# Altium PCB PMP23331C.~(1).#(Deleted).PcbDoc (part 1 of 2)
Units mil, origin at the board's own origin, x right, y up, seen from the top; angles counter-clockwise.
Board outline 3600 x 3375 mil, 4 copper layers (Top Layer, Signal Layer 1, Signal Layer 2, Bottom Layer), stack 39.6 mil thick; 105 components, 60 nets, 271 pads, 76 vias.
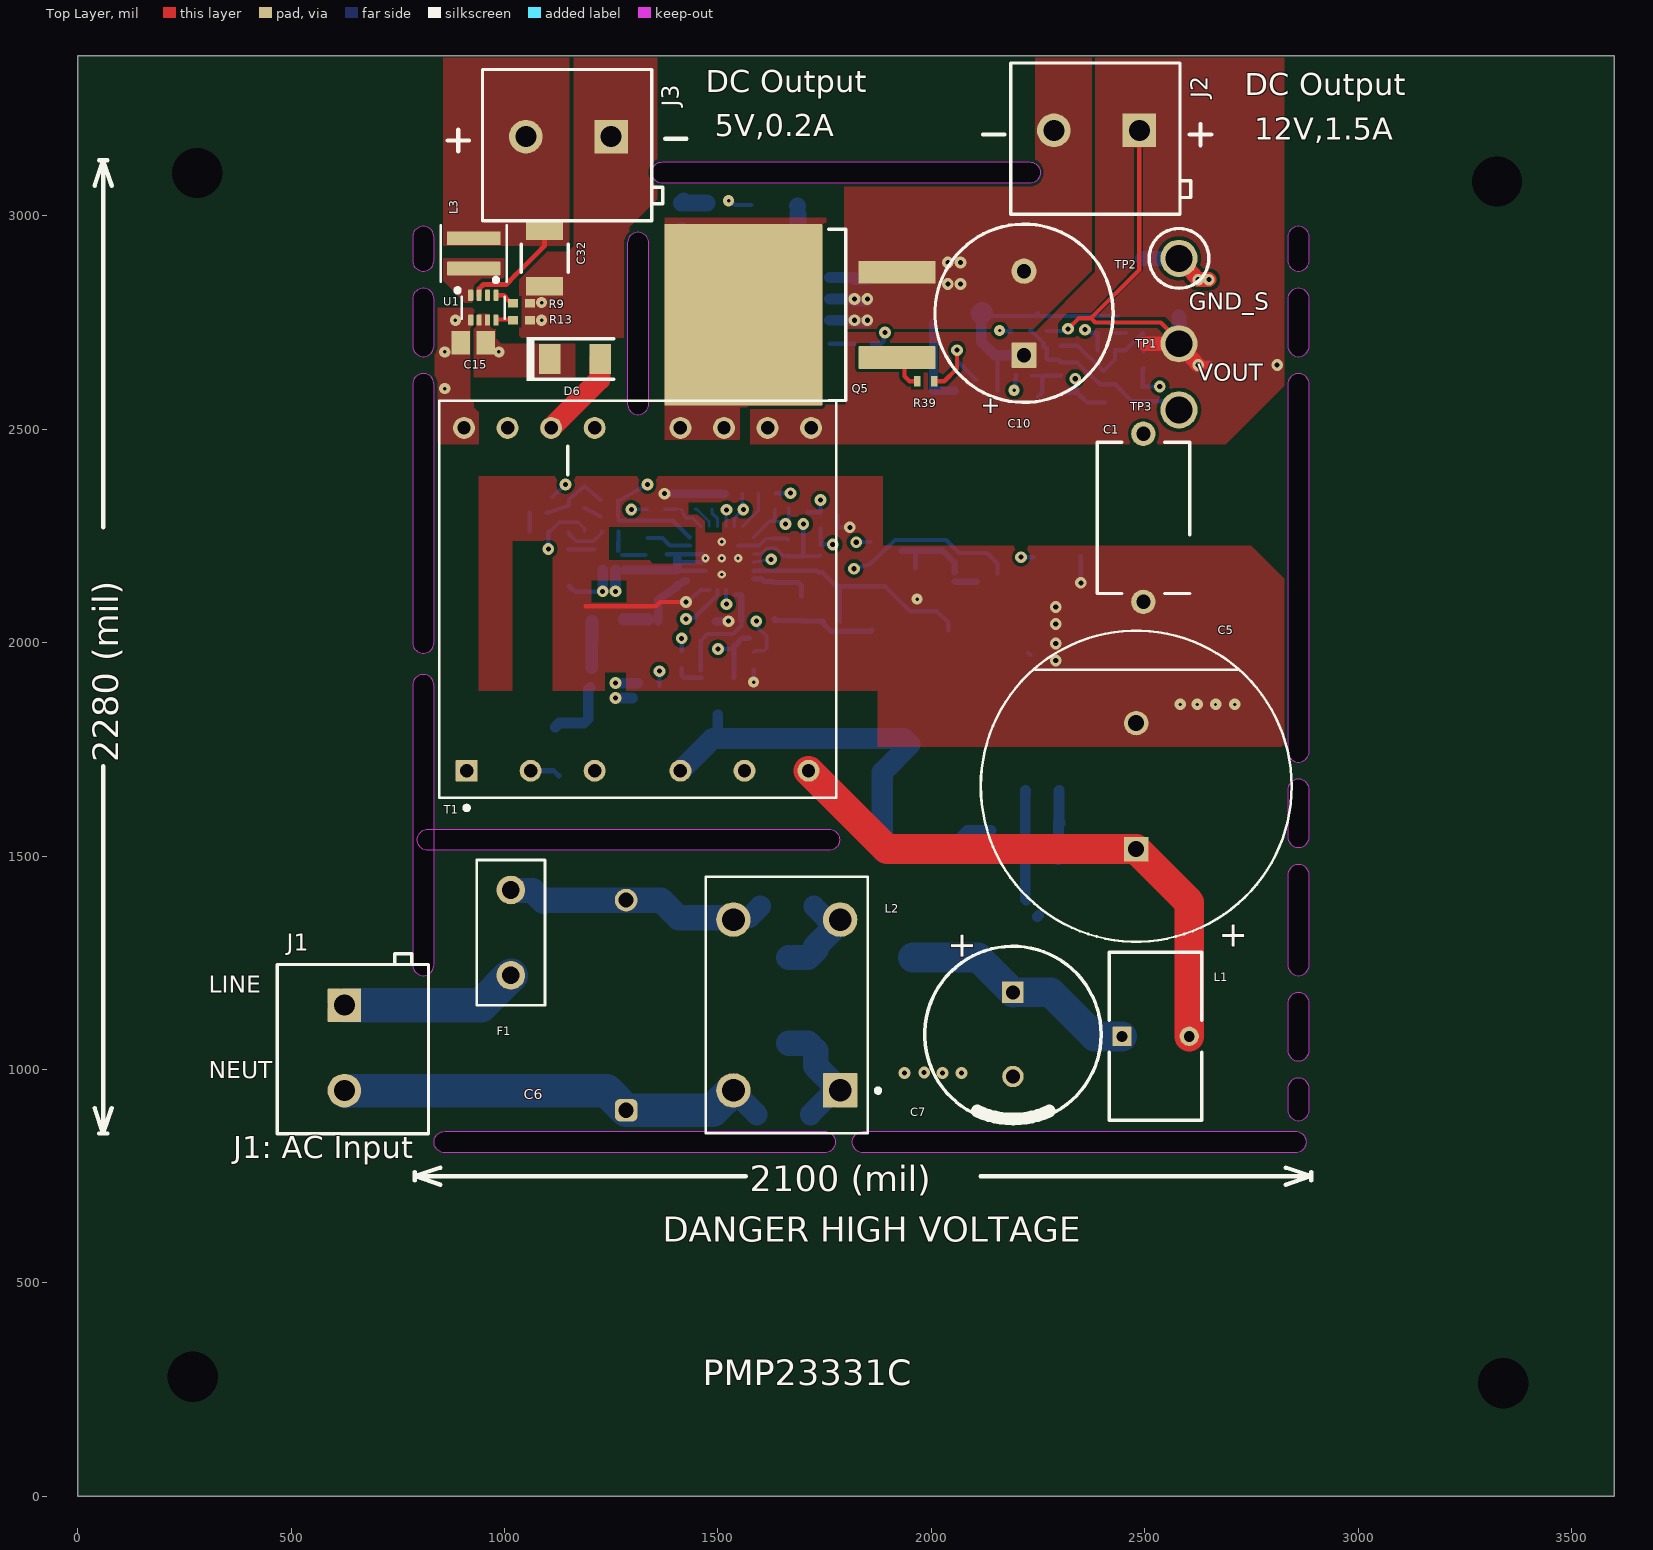
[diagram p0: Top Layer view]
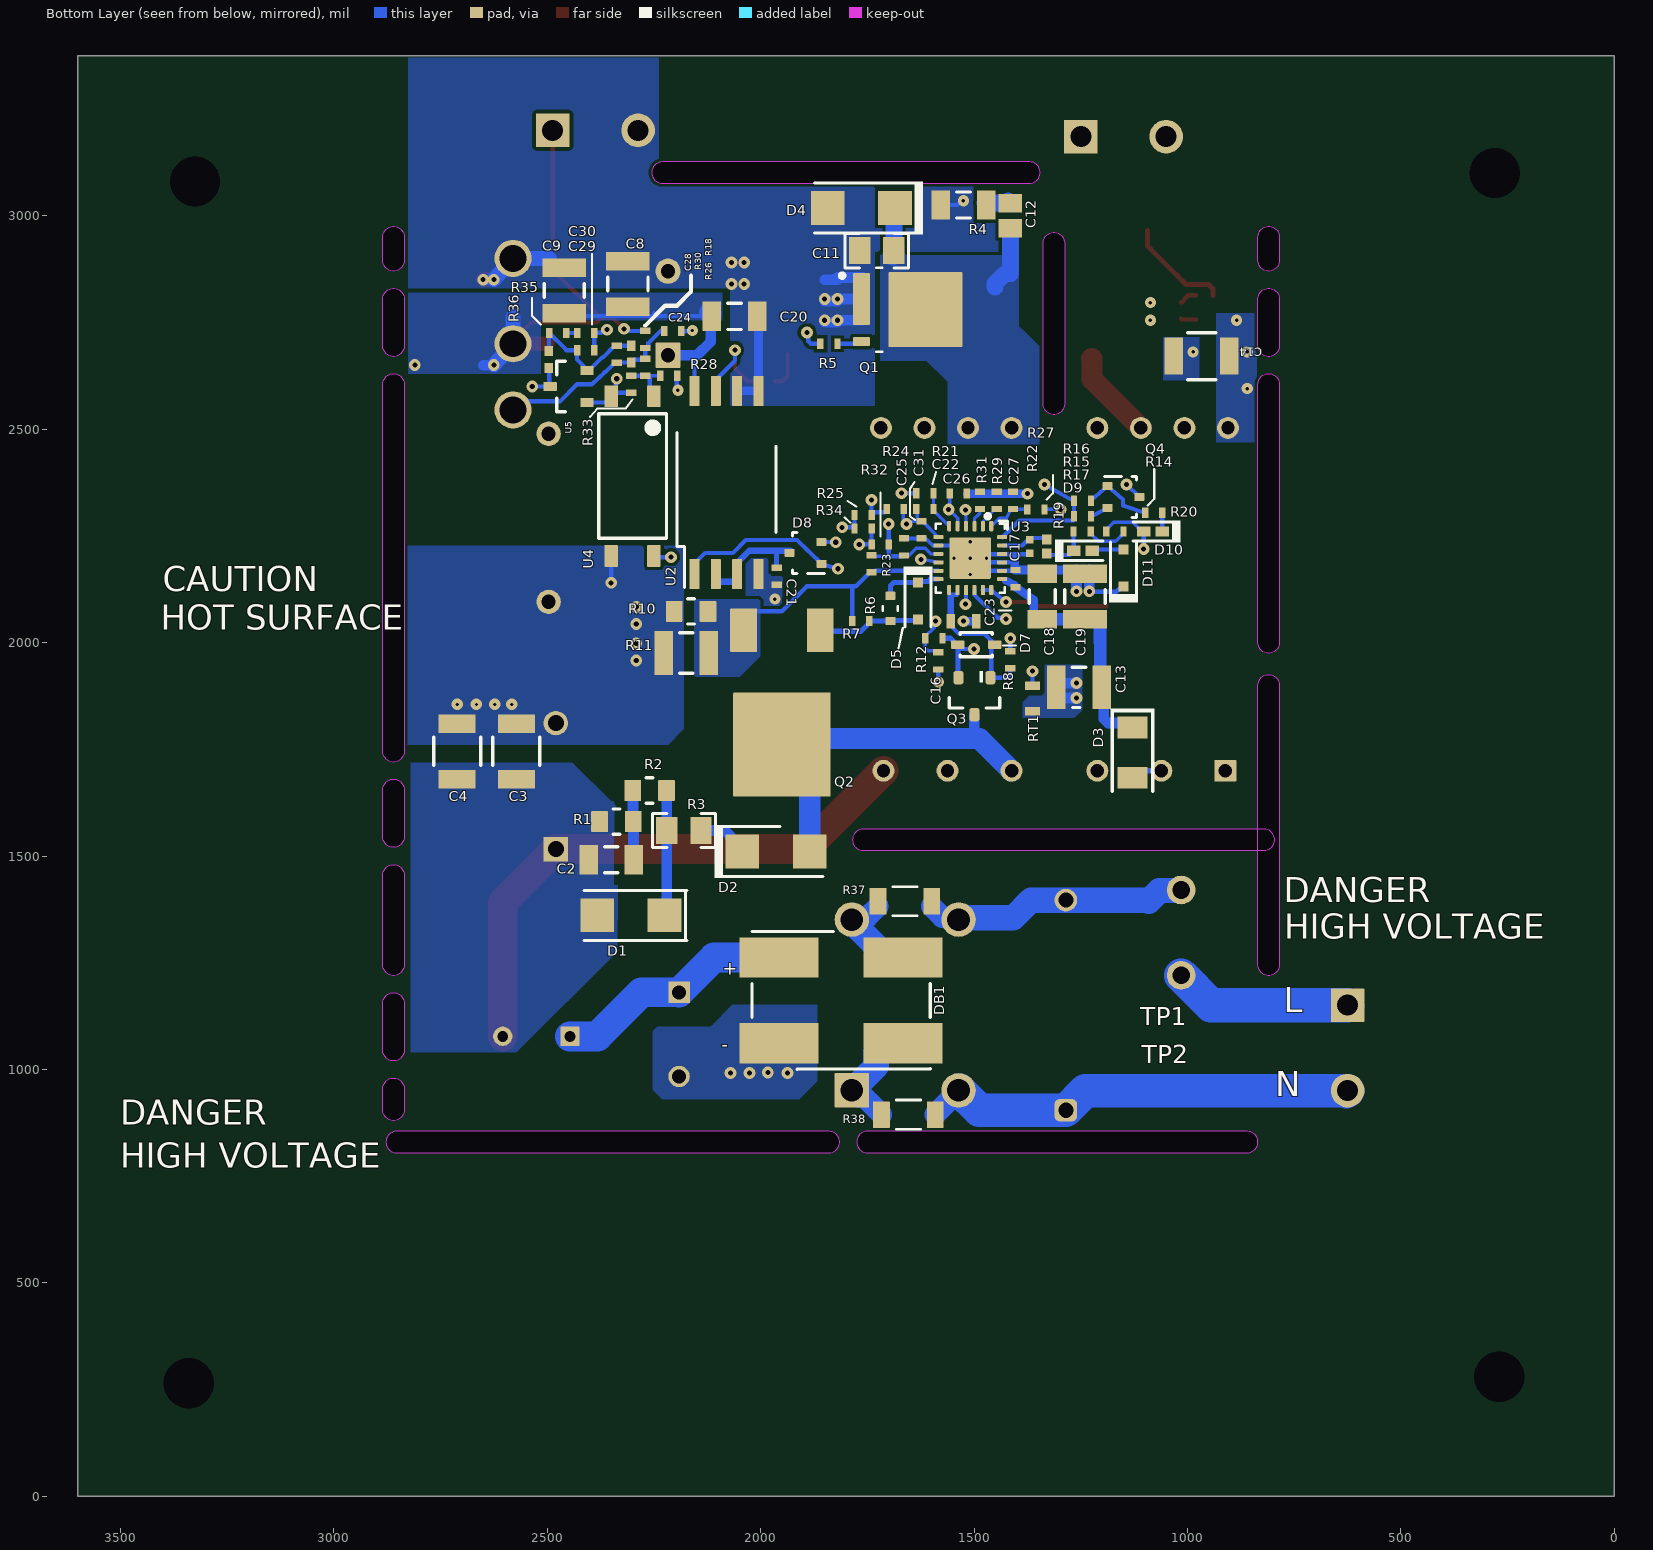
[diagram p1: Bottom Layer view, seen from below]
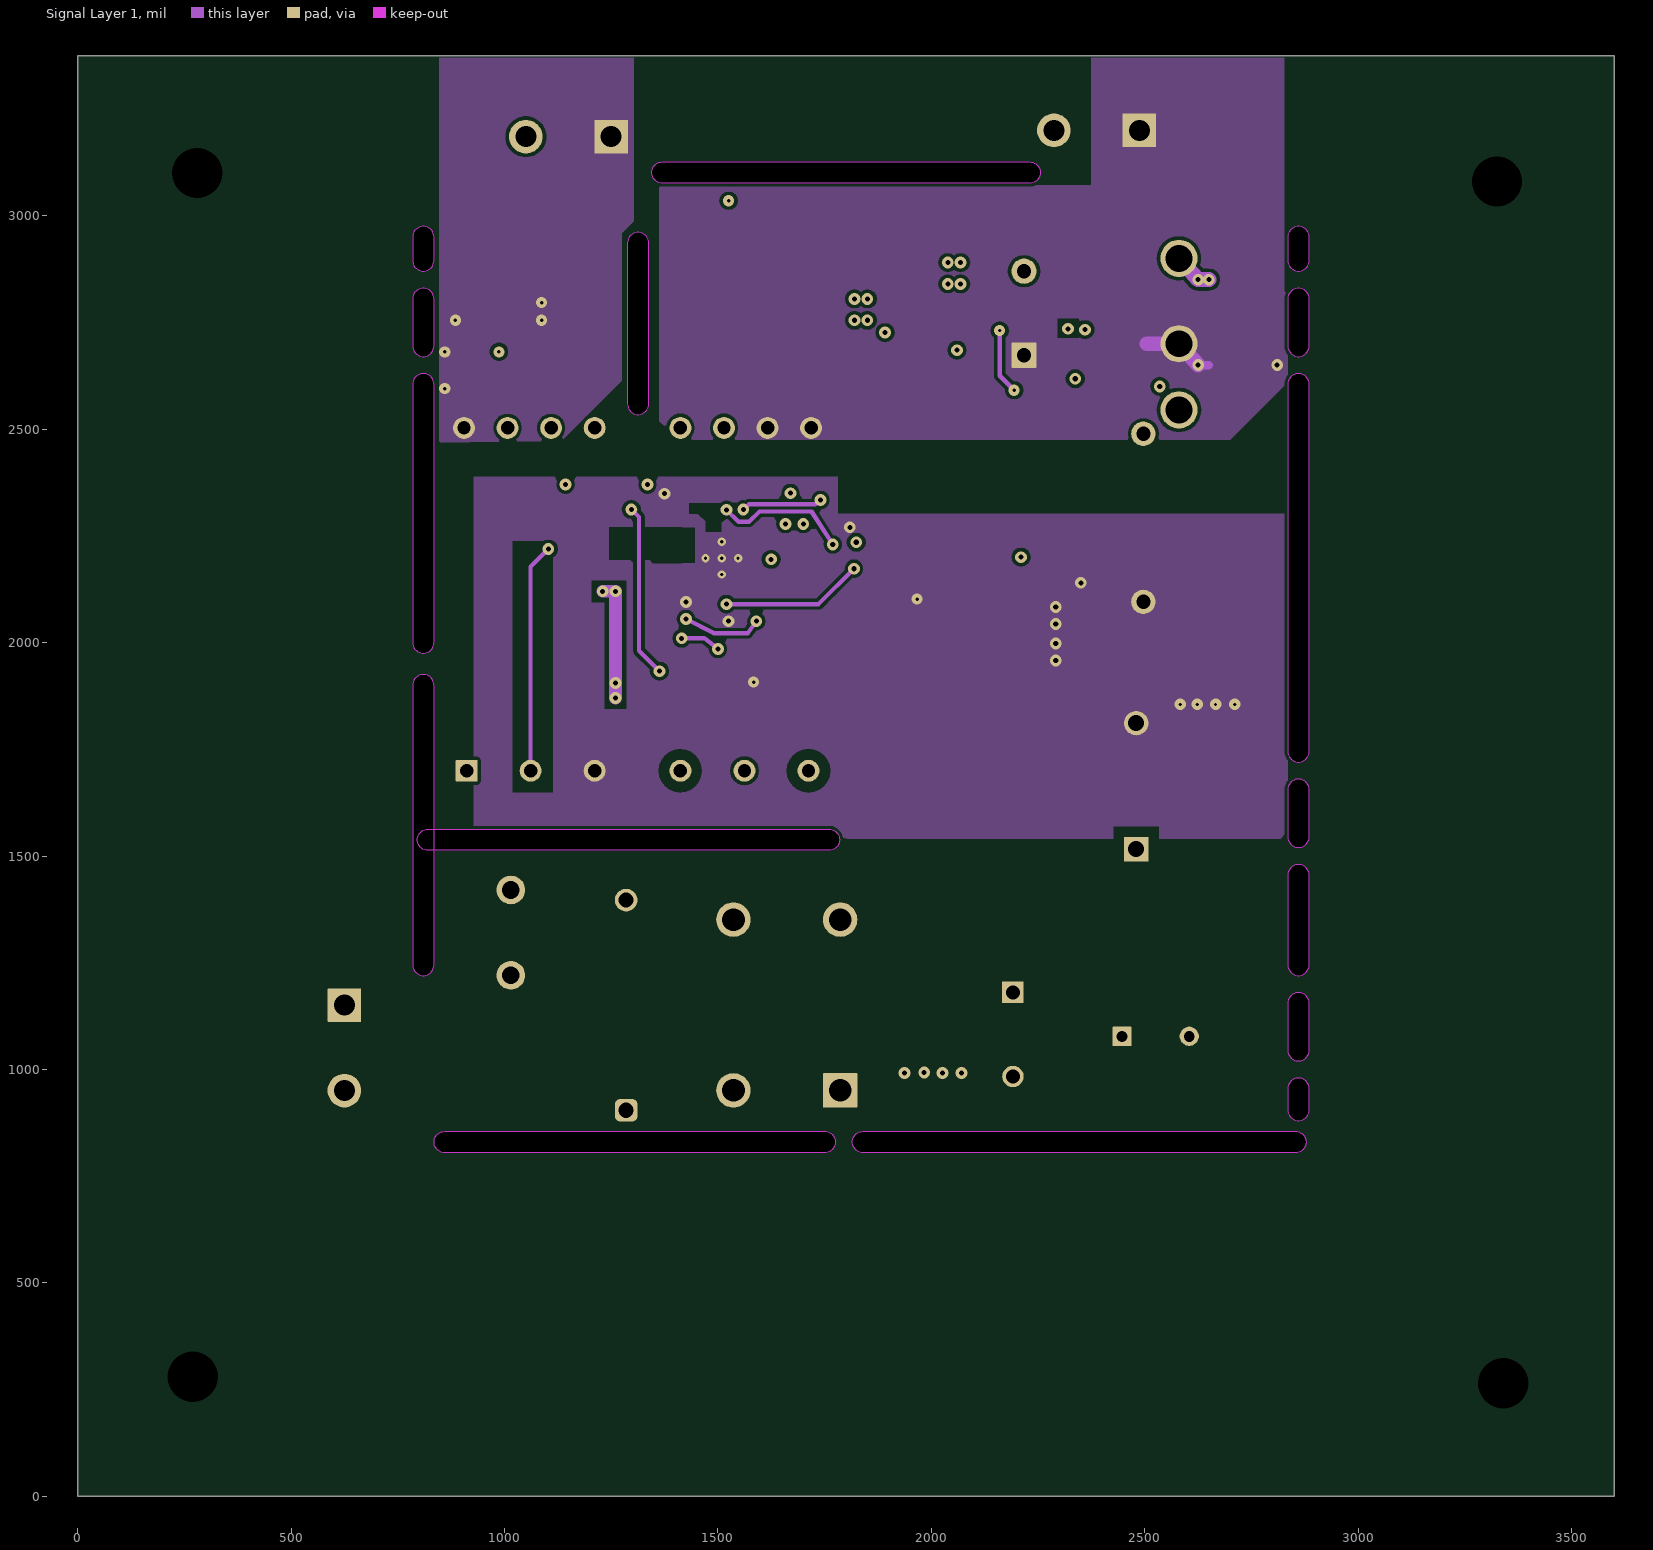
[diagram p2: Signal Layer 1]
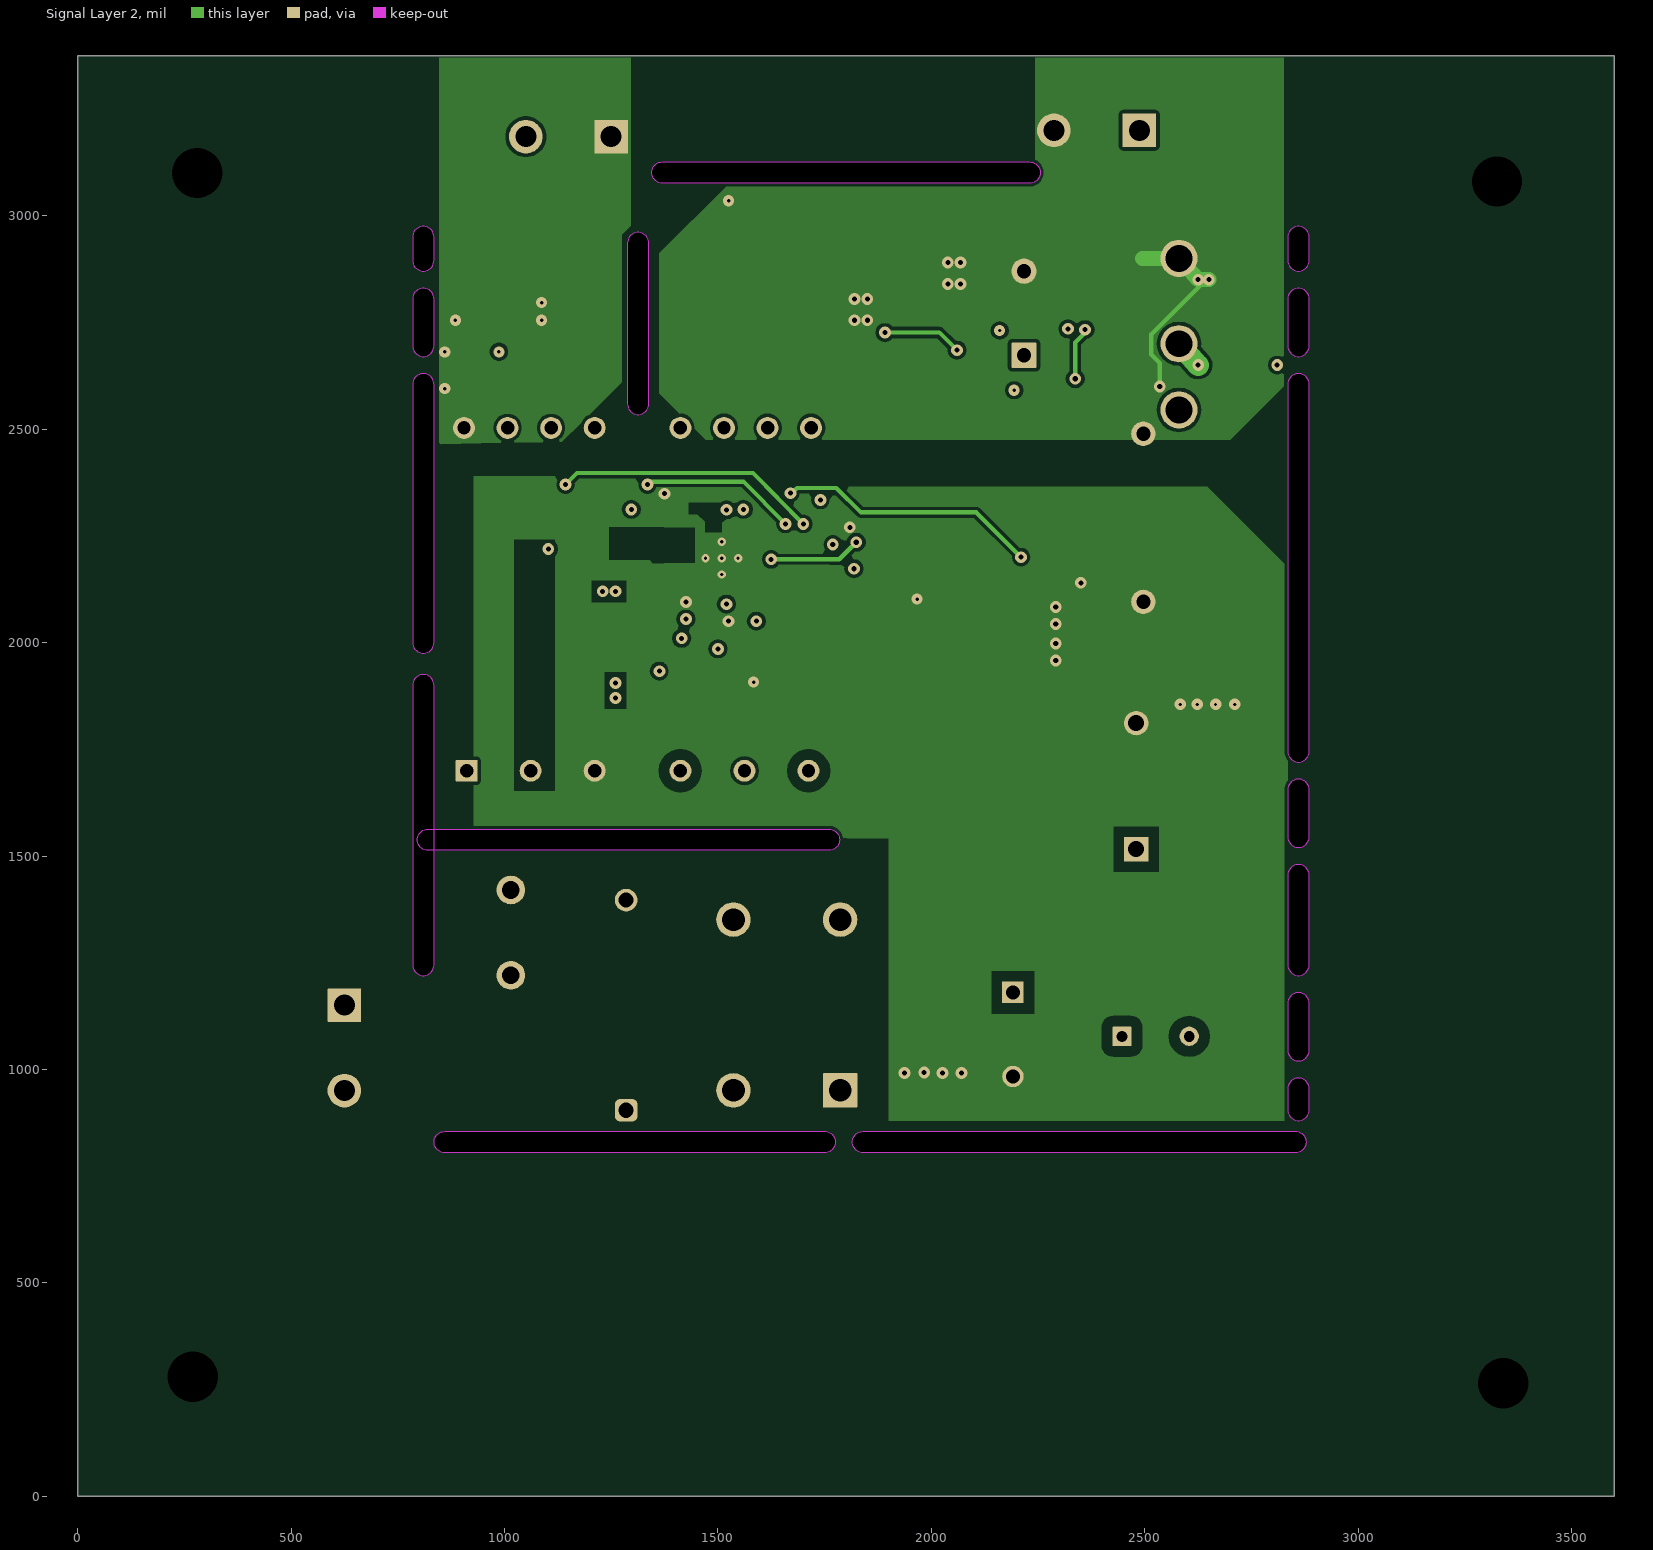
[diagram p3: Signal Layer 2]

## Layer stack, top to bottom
Top Solder: solder mask 0.4, Solder Resist, Dk 3.5
Top Layer: signal copper 1.4
Dielectric 1: prepreg 8, FR-4, Dk 4.2
Signal Layer 1: signal copper 1.4
Dielectric 2: core 18, FR-4, Dk 4.2
Signal Layer 2: signal copper 1.4
Dielectric 3: prepreg 8, FR-4, Dk 4.2
Bottom Layer: signal copper 1.4
Bottom Solder: solder mask 0.4, Solder Resist, Dk 3.5

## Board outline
0,0 3600,0 3600,3375 0,3375
cut-out: 1287.98,2559 ccw(c1313,2559) 1338.02,2559 1338.02,2936 ccw(c1313,2936) 1287.98,2936
cut-out: 821,1512.97 cw(c821,1537.99) 821,1563 1760,1563 cw(c1760,1537.99) 1785.02,1537.99 cw(c1760,1537.98) 1760,1512.97
cut-out: 1839.77,804.99 cw(c1839.77,830) 1839.77,855.01 2852.67,855.01 cw(c2852.67,830) 2877.69,830 cw(c2852.67,830) 2852.67,804.99
cut-out: 1370,3075.97 cw(c1370,3100.98) 1370,3126 2230,3126 cw(c2230,3100.98) 2255.01,3100.98 cw(c2230,3100.98) 2230,3075.97
cut-out: 2834.99,2895 ccw(c2860,2895) 2885.01,2895 2885.01,2950 ccw(c2860,2950) 2834.99,2950
cut-out: 2834.99,2695 ccw(c2860,2695) 2885.01,2695 2885.01,2805 ccw(c2860,2805) 2834.99,2805
cut-out: 2834.99,1545 ccw(c2860,1545) 2885.01,1545 2885.01,1655 ccw(c2860,1655) 2834.99,1655
cut-out: 2834.99,1245 ccw(c2860,1245) 2885.01,1245 2885.01,1455 ccw(c2860,1455) 2834.99,1455
cut-out: 2834.99,1045 ccw(c2860,1045) 2885.01,1045 2885.01,1155 ccw(c2860,1155) 2834.99,1155
cut-out: 2834.99,905 ccw(c2860,905) 2885.01,905 2885.01,955 ccw(c2860,955) 2834.99,955
cut-out: 860,804.99 cw(c860,830) 860,855.01 1750,855.01 cw(c1750,830) 1775.01,830 cw(c1750,830) 1750,804.99
cut-out: 784.98,1245 ccw(c810,1245) 835.02,1245 835.02,1900 ccw(c810,1900) 784.98,1900
cut-out: 784.98,2695 ccw(c810,2695) 835.02,2695 835.02,2805 ccw(c810,2805) 784.98,2805
cut-out: 784.98,2000 ccw(c810,2000) 835.02,2000 835.02,2605 ccw(c810,2605) 784.98,2605
cut-out: 784.98,2895 ccw(c810,2895) 835.02,2895 835.02,2950 ccw(c810,2950) 784.98,2950
cut-out: 2834.99,1745 ccw(c2860,1745) 2885.01,1745 2885.01,2605 ccw(c2860,2605) 2834.99,2605

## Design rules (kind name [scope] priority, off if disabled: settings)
AcuteAngle [All] p1: minimum=5.00000000000000E+0000 checktracksonly=FALSE
AssemblyTestPointUsage [All] p1: valid=2
BoardOutlineClearance BoardOutlineClearance_MountingHoles [OnCopper and InComponentClass('Mounting Holes')] p1: gap=15 ignorepadtopadclearanceinfootprint=FALSE
BoardOutlineClearance BoardOutlineClearance_Poly [OnCopper and InPoly] p2: gap=3.94 ignorepadtopadclearanceinfootprint=FALSE
BoardOutlineClearance [OnCopper and Not InComponentClass('Logo') and not InComponentClass('FiducialMark') and not InRegion(1000,500,4000,800)] p3: gap=4.53 ignorepadtopadclearanceinfootprint=FALSE
Clearance Clearance_HV [InNetClass('HV') vs not OnMultiLayer] p1: gap=25 ignorepadtopadclearanceinfootprint=TRUE // 1mm Clearance
Clearance Clearance_Keepouts [((IsTrack Or IsArc) And Not InPoly) And IsFree and IsKeepOut vs ((IsTrack Or IsArc) And Not InPoly) And IsFree and IsKeepOut] p2: gap=0 ignorepadtopadclearanceinfootprint=FALSE
Clearance Clearance_Poly [InPolygon] p3: gap=8 ignorepadtopadclearanceinfootprint=FALSE except(0: Arc-Hole Track-Hole SMDPad-Hole THPad-Hole Via-Hole Fill-Hole Poly-Hole Region-Hole Text-Hole)
Clearance [not InComponentClass('FiducialMark') vs not InComponentClass('FiducialMark')] p4: gap=6 ignorepadtopadclearanceinfootprint=FALSE
ComponentClearance ComponentClearance_MountingHoles_FiducialMarks [InComponentClass('Mounting Holes') vs InComponentClass('FiducialMark')] p1: gap=10 collisioncheckmode=3 verticalgap=10 showdistances=FALSE
ComponentClearance ComponentClearance_Shunt [InComponentClass('Header') vs InComponentClass('Shunt')] p2: gap=0 collisioncheckmode=3 verticalgap=0 showdistances=FALSE
ComponentClearance ComponentClearance_Logo [InComponentClass('Logo')] p3: gap=5 collisioncheckmode=3 verticalgap=0 showdistances=FALSE
ComponentClearance ComponentClearance_ScrewToNut [(HasFootprint('NY PMS 440 0025 PH')) vs (HasFootprint('Keystone_1902C'))] p4: gap=5 collisioncheckmode=3 verticalgap=10 showdistances=FALSE
ComponentClearance ComponentClearance_MountingHoles [InComponentClass('Mounting Holes')] p5: gap=10 collisioncheckmode=3 verticalgap=100000 showdistances=FALSE
ComponentClearance ComponentClearance_SmallPassives [HasFootprint('0201*') or HasFootprint('0402*') or HasFootprint('0508') or HasFootprint('0603*') or HasFootprint('0612') or HasFootprint('0805*') or HasFootprint('0815*') or HasFootprint('0830*') or HasFootprint('1206*') or HasFootprint('1210*') or HasFootprint('1808*') or HasFootprint('1812*') or HasFootprint('1825*') or HasFootprint('2010*') or HasFootprint('2220*') or HasFootprint('2225*') or HasFootprint('2512*') or HasFootprint('2728*') or HasFootprint('3518*') vs HasFootprint('0201*') or HasFootprint('0402*') or HasFootprint('0508') or HasFootprint('0603*') or HasFootprint('0612') or HasFootprint('0805*') or HasFootprint('0815*') or HasFootprint('0830*') or HasFootprint('1206*') or HasFootprint('1210*') or HasFootprint('1808*') or HasFootprint('1812*') or HasFootprint('1825*') or HasFootprint('2010*') or HasFootprint('2220*') or HasFootprint('2225*') or HasFootprint('2512*') or HasFootprint('2728*') or HasFootprint('3518*')] p6: gap=8 collisioncheckmode=3 verticalgap=10 showdistances=FALSE
ComponentClearance ComponentClearance_THtoSMT [IsThruComponent vs IsSMTComponent] p7: gap=10 collisioncheckmode=3 verticalgap=30 showdistances=FALSE
ComponentClearance ComponentClearance_THtoTH [IsThruComponent vs IsThruComponent] p8: gap=2 collisioncheckmode=3 verticalgap=30 showdistances=FALSE
ComponentClearance [All] p9: gap=8 collisioncheckmode=3 verticalgap=10 showdistances=FALSE
DiffPairsRouting [All] p1: maxlimit=100 minlimit=10 mostfreqgap=10 toplayer_minwidth=15 toplayer_maxwidth=15 toplayer_prefwidth=15 midlayer1_minwidth=15 midlayer1_maxwidth=15 midlayer1_prefwidth=15 midlayer2_minwidth=15 midlayer2_maxwidth=15 midlayer2_prefwidth=15 bottomlayer_minwidth=15 bottomlayer_maxwidth=15 bottomlayer_prefwidth=15 maxuncoupledlength=1000
FabricationTestPointUsage TestPointUsage [All] p1: valid=2 allowmultiple=FALSE
FabricationTestpoint Testpoint [All] p1: side=3 testpointundercomponent=TRUE minsize=40 maxsize=100 preferedsize=60 minholesize=0 maxholesize=40 preferedholesize=32 testpointgrid=1 allowsidetop=TRUE allowsidebottom=TRUE usegrid=TRUE gridtolerance=0.01
FanoutControl Fanout_LCC [IsLCC] p1: bgadir=Out bgaviamode=Centered fanoutstyle=Auto fanoutdirection=Alternating viagrid=1 // Fanout_LCC (Default Rule)
FanoutControl Fanout_BGA [IsBGA] p2: bgadir=Out bgaviamode=Centered fanoutstyle=Auto fanoutdirection=Alternating viagrid=1 // Fanout_BGA (Default Rule)
FanoutControl Fanout_Default [All] p4: bgadir=Out bgaviamode=Centered fanoutstyle=Auto fanoutdirection=Alternating viagrid=1 // Fanout_Default (Default Rule)
FanoutControl Fanout_Small [(CompPinCount < 5)] p5: bgadir=Out bgaviamode=Centered fanoutstyle=Auto fanoutdirection=OutThenIn viagrid=1 // Fanout_Small (Default Rule)
HoleSize [All] p1: absolutevalues=TRUE maxlimit=251 minlimit=7.87 maxpercent=80.000 minpercent=20.000
HoleToHoleClearance [All] p1: gap=7.87 allowstackedmicrovias=TRUE
MinimumAnnularRing MinimumAnnularRing_ThermalPadVias [IsVia and InAnyComponent] p1: minimumring=5.91
MinimumAnnularRing [All] p2: minimumring=5
MinimumSolderMaskSliver MinimumSolderMaskSliver_Logo [InComponentClass('Logo') vs InComponentClass('Logo')] p1: minsoldermaskwidth=0
MinimumSolderMaskSliver [All] p2: minsoldermaskwidth=1
PlaneConnect [All] p1: planeconnectstyle=Direct reliefexpansion=10 reliefentries=4 reliefconductorwidth=10 reliefairgap=10
PolygonConnect [All] p1: connectstyle=Direct reliefconductorwidth=15.75 reliefentries=4 polygonreliefangle="90 Angle" airgapwidth=7.87
RoutingVias ThermalPadVias [IsVia and InAnyComponent] p1: holewidth=7.87 width=19.68 viastyle="Through Hole" minholewidth=7.87 minwidth=19.68 maxholewidth=12.99 maxwidth=23.62
RoutingVias [All] p2: holewidth=16 width=34 viastyle="Through Hole" minholewidth=7.87 minwidth=26 maxholewidth=40 maxwidth=65
SilkToBoardRegionClearance [Not ((IsComment or IsDesignator) And (Hide <> 'False')) and not InRegion(1000,500,4000,800)] p1:
SilkToSilkClearance SilkToSilkClearance_Pb-FreeLogo [(HasFootprint('Pb-Free_Overlay_Medium') OR HasFootprint('Pb-Free_Overlay_Small')) vs (HasFootprint('Pb-Free_Overlay_Medium') OR HasFootprint('Pb-Free_Overlay_Small'))] p1: silktosilkclearance=0
SilkToSilkClearance [All] p2: silktosilkclearance=0.5
SilkToSolderMaskClearance SilkToComponentPadClearance [IsPad and InAnycomponent] p1: minsilkscreentomaskgap=0.3 clearancetoexposedcopper=TRUE
SilkToSolderMaskClearance "Silk to Solder Mask Opening" [All] p2: minsilkscreentomaskgap=0 clearancetoexposedcopper=FALSE
SolderMaskExpansion [All] p1: expansion=1.97 istentingtop=FALSE
Width [All] p1: maxlimit=100 minlimit=5 preferedwidth=10 checkconnectedcopper=TRUE
14 further rules are at their usual default settings.

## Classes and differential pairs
net class Secondary: GND_S
net class Primary: GND_P
net class HV: NetC7_1 Vbulk VSWN

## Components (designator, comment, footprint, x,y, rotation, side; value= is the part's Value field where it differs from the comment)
C1 "C921U222MVVDBA7317" C900_9x13 2496.65,2292.24 r270 top value=2200pF
C2 "GRM31BR72J102KW01L" 1206L 2350,1490.98 r180 bottom value=1000pF
C3 "C1210C104KBRAC7800" 1210_280 2572.13,1745 r270 bottom value=0.1uF
C4 "C1210C104KBRAC7800" 1210_280 2711,1745 r270 bottom value=0.1uF
C5 "450BXW22MEFR18X16" FP-450BXW22MEFR18X16_RADIAL-MFG 2479.8,1663.67 r270 top
C6 "890324024003" WCAP-FTX2_1500x850 1285,1150.47 r90 top value=0.33uF
C7 "UVC2G150MPD" UVC_1000x1600 2191,1082 r270 top value=15uF
C8 "GRM32ER71E226KE15L" 1210_270L 2311,2840 r90 bottom value=22uF
C9 "GRM32ER71E226KE15L" 1210_270L 2460,2825 r90 bottom value=22uF
C10 "APSG200ELL681MJB5S" PSG_1000x1150 2217,2771.43 r90 top value=680uF
C11 "C2012X7R2E102K085AA" 0805_HV 1728,2918 r180 bottom value=1000pF
C12 "GRM21AR72E102KW01D" 0805L 1415,3000 r270 bottom value=1000pF
C13 "GMK325BJ226MM-P" 1210L 1254.15,1895 r180 bottom value=22uF
C14 "C1210C106K3RACTU" 1210_280 967,2671 r180 bottom value=10uF
C15 "CGA4J1X7R1E475K125AC" 0805L 926.53,2702 r180 top value=4.7uF
C16 "GCM1555C1H220JA16D" 0402S 1583.77,1957 r90 bottom value=22pF
C17 "GRM155R71H104ME14D" 0402S 1403,2150 r90 bottom value=0.1uF
C18 "C3216X5R1H106K160AB" 1206_180L 1340,2108 r90 bottom value=10uF
C19 "GMK325BJ226MM-P" 1210L 1240,2108 r270 bottom value=22uF
C20 "C1206C106J3RACAUTO" 1206_180L 2061,2764 r180 bottom value=10uF
C21 "GRM155R71H104ME14D" 0402S 1962.37,2155 r270 bottom value=0.1uF
C22 "GRM155R71H331KA01D" 0402S 1615,2313 r180 bottom value=330pF
C23 "CGA3E1X7R1V105K080AC" 0603S 1525,2050 r180 bottom value=1uF
C24 "GRM155R71H153KA12D" 0402S 2206,2730 r0 bottom value=0.015uF
C25 "GRM1555C1H101JA01D" 0402S 1664,2224 r90 bottom value=100pF
C26 "GRM155R71H331KA01D" 0402S 1537.14,2349.3 r180 bottom value=330pF
C27 "GRM1555C1H101JA01D" 0402S 1409,2333 r270 bottom value=100pF
C28 "GCM1555C1H220JA16D" 0402S 2337.06,2675.67 r270 bottom value=22pF
C29 "GCM1555C1H220JA16D" 0402S 2410,2685 r0 bottom value=22pF
C30 "GRM155R71H103KA88D" 0402S 2410,2725 r180 bottom value=0.01uF
C31 "GRM155R71C224KA12D" 0402S 1623,2264 r270 bottom value=0.22uF
C32 "GCM32ER71C226KE19L" 1210_280 1094.16,2900 r270 top value=22uF
D1 "SMAJ150A" SMA 2304,1361 r0 bottom value=150V
D2 "MRA4007T3G" SMA 1964,1510.66 r180 bottom value=1000V
D3 "CSFMT104-HF" SOD-123H 1128.75,1742.24 r270 bottom value=200V
D4 "SMAJ120A" SMA 1764,3018 r0 bottom value=120V
D5 "BAS316,115" SOD-323 1631,2097 r270 bottom value=100V
D6 "CSFMT104-HF" SOD-123H 1165.21,2664.48 r0 top value=200V
D7 "CDSOD323-T18C" FP-CDSOD323-T18C_SOD323-MFG 1495,1995 r180 bottom value=18V
D8 "BAS40W-05-7-F" SOT-323 1895,2210 r0 bottom value=40V
D9 "1N4148X-TP" SOD-523 1245,2215 r180 bottom value=75V
D10 "BZT585B39T-7" SOD-523 1081,2260 r0 bottom value=39V
D11 "SZMM3Z27VST1G" SOD-323 1150,2175 r90 bottom value=27V
DB1 "Z4DGP406L-HF" Z4-D 1811.67,1161.85 r180 bottom value=600V
F1 "39213150000" FUSE_392 1015,1320.47 r270 top
J1 "ED120/2DS" On-Shore_ED120_2DS 625,1050.47 r270 top
J2 "ED120/2DS" On-Shore_ED120_2DS 2387,3200 r180 top
J3 "ED120/2DS" On-Shore_ED120_2DS 1150,3185 r180 top
L1 "7447052" FP-7447052_PTH_D10MM0-MFG 2525.33,1077.65 r90 top
L2 "RLTI-1387" FP-RLTI-1387_PTH_CMC_0IN38_0IN60-MFG 1661.31,1151.02 r90 top
L3 "XGL3530-332MEC" FP-XGL3530_SMT_IND_3MM2_3MM5-MFG 928,2911.72 r90 top value=3.3uH
Q1 "BSC074N15NS5ATMA1" FP-BSC074N15NS5ATMA1_PG-TSON-8-3-MFG 1655.44,2780 r270 bottom
Q2 "IPD70R1K4P7S" DPAK 1950,1895 r270 bottom value=800V
Q3 "CPC3982TTR" SOT-23L 1499.2,1874.45 r270 bottom value=800V
Q4 "MMST3906-7-F" SOT-323 1150.02,2341 r180 bottom value="40 V"
Q5 "IPB048N15N5LF" FP-IPB042N10N3GATMA1_D2PAK-MFG 1692.21,2767.74 r90 top
R1 "CRCW0805470KJNEA" 0805_HV1 2337.75,1580.68 r0 bottom value=470k
R2 "CRCW080515R0JNEA" 0805_HV1 2260,1653.43 r0 bottom value=15
R3 "CRCW080520R5FKEA" 0805_HV 2179.8,1559.88 r0 bottom value=20.5
R4 "CRCW120610R0JNEA" 1206L 1525,3025 r180 bottom value=10
R5 "CSR0402FK1R00" 0402S 1840,2700 r180 bottom value=1.00
R6 "RK73H1JTTD1000F" FP-RK73H1JTTD1000F_0603-MFG 1696,2080 r270 bottom
R7 "CRCW040210K0FKED" 0402S 1765.07,2050.47 r180 bottom value=10.0k
R8 "CRCW04021M00JNED" 0402S 1415,1960 r270 bottom value=1.0Meg
R9 "CRCW040280K6FKED" 0402L 1040,2795 r180 top value=80.6k
R10 "ERJ-6RQFR68V" 0805_HV1 2162.75,2073.15 r0 bottom value=0.68
R11 "MCR25JZHFLR220" 1210L 2174.24,1975.71 r180 bottom value=0.22
R12 "CRCW0402511RFKED" 0402S 1593.9,2010 r180 bottom value=511
R13 "CRCW040227K4FKED" 0402L 1040,2755 r180 top value=27.4k
R14 "RC0402FR-0725K5L" 0402S 1170,2260 r0 bottom value=12.4k
R15 "CRCW040227K4FKED" 0402S 1246,2296 r180 bottom value=27.4k
R16 "CRCW04021K00FKED" 0402S 1246,2332 r180 bottom value=1.00k
R17 "RC0402FR-0725K5L" 0402S 1247,2260 r0 bottom value=2.10k
R18 "RC0402JR-070RL" 0402S 2270,2710 r270 bottom value=0
R19 "RC0402JR-070RL" RESC1005X40X25NL05T10 1330,2225 r270 bottom value=0
R20 "CRCW040210K0FKED" 0402S 1079,2304 r180 bottom value=10.0k
R21 "CRCW040220K0FKED" 0402S 1615,2350 r0 bottom value=20.0k
R22 "ERJ-2RKF9311X" RESC1005X40X25LL05T05 1370,2225 r90 bottom value=9.31k
R23 "CRCW0402340RFKED" 0402S 1740,2184.41 r270 bottom value=340
R24 "CRCW0402191KFKED" 0402S 1685,2313 r0 bottom value=191k
R25 "CRCW040239K2FKED" 0402S 1760,2299 r0 bottom value=39.2k
R26 "RC0402FR-0710KL" 0402S 2270,2645 r90 bottom value=10.0k
R27 "CRCW04023K32FKED" 0402S 1355,2312 r0 bottom value=3.32k
R28 "CRCW0402511RFKED" 0402S 2215,2625 r180 bottom value=511
R29 "CRCW0402169KFKED" 0402S 1446.59,2332.88 r270 bottom value=169k
R30 "CRCW0402154KFKED" 0402L 2303.15,2675.67 r270 bottom value=154k
R31 "CRCW040293K1FKED" 0402S 1485.96,2332.88 r270 bottom value=93.1k
R32 "CRCW04021M00JNED" 0402S 1720,2230 r180 bottom value=1.0Meg
R33 "CRCW04028K66FKED" 0402S 2303.15,2605 r90 bottom value=8.66k
R34 "CRCW04020000Z0EDHP" 0402S 1760,2267 r180 bottom value=0
R35 "CRCW040210K0FKED" 0402S 2475,2725 r0 bottom value=10.0k
R36 "CRCW040240K2FKED" 0402L 2496.65,2662.99 r90 bottom value=40.2k
R37 "RMCF1206ZT0R00" FP-RMCF1206ZT0R00_1206-MFG 1662.06,1394 r0 bottom value=0
R38 "RMCF1206ZT0R00" FP-RMCF1206ZT0R00_1206-MFG 1654,894 r0 bottom value=0
R39 "CSR0402FK1R00" 0402S 1987,2612 r180 top value=1.00
RT1 "NCP18WB473J03RB" 0603S 1362.93,1868.9 r270 bottom value=47k
T1 "RLTI-1457" FP-RLTI-1457_PTH14_0IN93_0IN93-MFG 1311.71,2101.25 r90 top
TP1 "VOUT" Keystone5012 2580,2700 r90 top
TP2 "GND_S" Keystone5011 2580,2900 r90 top
TP3 "VOUT_A" Keystone5012 2580,2545 r90 top
U1 "TPS629203DRLR" DRL0008A-MFG 950.47,2784.48 r270 top
U2 "UCC5304DWV" DWV0008A 2080,2375 r90 bottom locked
U3 "UCC28781QRTWRQ1" RTW0024B-MFG 1508.96,2197.72 r270 bottom
U4 "TLP383(GR-TPL,E" FP-TLP383(GR-TPL,E_SO6-4-MFG 2300,2390 r270 bottom locked
U5 "ATL431AIDBZR" DBZ0003A_L 2450,2600 r0 bottom

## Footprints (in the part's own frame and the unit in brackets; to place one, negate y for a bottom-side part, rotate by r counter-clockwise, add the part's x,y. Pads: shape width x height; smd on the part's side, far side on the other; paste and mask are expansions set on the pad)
0402L [mm] "0402 from SM-752 data"
  rect 0.6x0.5 smd: 1(-0.5,0) 2(0.5,0)
  body extent -0.55,-0.3 0.55,0.3, height 0.6
0402S [mil] "Based on C0402S footprint from PADS legacy"
  rect 15x24 smd: 1(-20,0) 2(20,0)
  body extent -22,-12 22,12, height 24
0603S [mil]
  rect 20x35 smd: 1(-30,0) 2(30,0)
  body extent -34,-19 34,19, height 39
0805_HV [mil] "0805 with 30mil clearance between pads"
  rect 50x63 smd: 1(-40,0) 2(40,0)
  silkscreen extent -74,-40 74,40, body extent -43,-29 43,29, height 57
0805_HV1 [mm] "Custom footprint based on analyzing multiple manufacturer recommendations"
  rrect10% 1x1.25 smd: 1(-1,0) 2(1,0)
  silkscreen extent -0.2,-0.75 0.2,0.75, body extent -1.1,-0.72 1.1,0.73, height 1.45
0805L [mm] "0805 from SM-752 data"
  rect 1.1x1.4 smd: 1(-0.75,0) 2(0.75,0)
  body extent -1.1,-0.72 1.1,0.72, height 1.45
1206_180L [mm] "1206_180"
  rect 1.1x1.75 smd: 1(-1.35,0) 2(1.35,0)
  silkscreen extent -0.4,-0.77 0.4,0.77, body extent -1.75,-0.95 1.75,0.95, height 1.8
1206L [mm] "1206 from SM-752 data"
  rect 1.1x1.75 smd: 1(-1.35,0) 2(1.35,0)
  silkscreen extent -0.4,-0.77 0.4,0.77, body extent -1.7,-0.9 1.7,0.9, height 1.35
1210_270L [mm] "1210"
  rect 1.1x2.6 smd: 1(-1.35,0) 2(1.35,0)
  silkscreen extent -0.4,-1.2 0.4,1.2, body extent -1.7,-1.35 1.7,1.35, height 2.7
1210_280 [mm] "SMD, 2-Leads, Body 3.6x2.8mm, Height 2.8mm"
  rect 1.1x2.2 smd: 1(-1.65,0) 2(1.65,0)
  silkscreen extent -0.84,-1.4 0.84,1.4, body extent -1.8,-1.4 1.8,1.4, height 2.8
1210L [mm] "1210 from SM-752 data"
  rect 1.1x2.6 smd: 1(-1.35,0) 2(1.35,0)
  silkscreen extent -0.4,-1.19 0.4,1.2, body extent -1.7,-1.35 1.7,1.35, height 1.35
C900_9x13 [mm] "Kemet"
  round 1.45 hole 0.85: 1(-5,0) 2(5,0)
  silkscreen extent -4.5,-2.75 4.5,2.76, body extent -4.49,-2.75 4.49,2.75, height 12.96
DBZ0003A_L [mm] "SOT23, 3-Leads, Body 2.9x1.3mm, Pitch 0.95mm, Lead Span 2.4mm, IPC High Density"
  rrect18% 0.8x0.55 smd: 1(-1.1,0.95) 2(-1.1,-0.95) 3(1.1,0)
  silkscreen extent 0.2,-1.5 0.7,1.5, body extent -1.26,-1.46 1.26,1.46, height 0.98
DPAK [mm] "D-PAK, 3-Pads, Body 6.22x6.73mm (max), TO-252AA using nominal STEP model"
  rrect6% 2.6x1.6 smd: 1(-3.4,2.28) 3(-3.4,-2.28)
  rrect2% 6.2x5.8 smd paste-3: 2(3.4,0)
  body extent -3.86,-3.29 5.84,3.29, height 2.48
DRL0008A-MFG [mm]
  rrect33% 0.67x0.3 smd paste+0 mask+0: 1(-0.74,0.75) 2(-0.74,0.25) 3(-0.74,-0.25) 4(-0.74,-0.75) 5(0.74,-0.75) 6(0.74,-0.25) 7(0.74,0.25) 8(0.74,0.75)
  silkscreen extent -1.77,-1.28 0.65,1.28, body extent -1.17,-1.35 1.17,1.35, height 0.25
DWV0008A [mm] "SOIC, 8-Leads, Body 5.95x7.6mm (max), Pitch 1.27mm"
  rrect17% 1.8x0.6 smd: 1(-5.45,1.905) 2(-5.45,0.635) 3(-5.45,-0.635) 4(-5.45,-1.905) 5(5.45,-1.905) 6(5.45,-0.635) 7(5.45,0.635) 8(5.45,1.905)
  silkscreen extent -6.25,-2.95 2.98,2.95, body extent -5.77,-2.92 5.77,2.93, height 2.67
FP-450BXW22MEFR18X16_RADIAL-MFG [mm]
  round 1.45 hole 0.95 paste-1000 mask+0: 1(-3.75,0)
  rect 1.45x1.45 hole 0.95 paste-1000 mask+0: 2(3.75,0)
  silkscreen extent -9.25,-9.25 9.25,9.25, body extent -9.35,-9.35 9.35,9.35, height 0.25
FP-7447052_PTH_D10MM0-MFG [mm]
  rrect9% 1.15x1.15 hole 0.65 paste-1000: 1(0,2)
  round 1.15 hole 0.65 paste-1000: 2(0,-2)
  silkscreen extent -5,-2.75 5,2.75, body extent -5.1,-2.85 5.1,2.85, height 0.25
FP-BSC074N15NS5ATMA1_PG-TSON-8-3-MFG [mm]
  rrect10% 3.08x1 smd paste-1000 mask-1000: 1-2-3(-0.635,-2.75)
  rrect19% 0.54x1 smd paste-1000 mask+0: 4(1.905,-2.75)
  rrect2% 4.45x4.4 smd paste-1000 mask-1000: 5-6-7-8(0,1.05)
  silkscreen extent -2.5,-4.03 2.5,-1.53, body extent -2.5,-3 2.5,3, height 1.1
FP-CDSOD323-T18C_SOD323-MFG [mm]
  rrect20% 0.8x0.5 smd paste+0 mask+0: 1(-1.1,0) 2(1.1,0)
  silkscreen extent -0.95,-0.72 0.95,0.72, body extent -1.27,-0.65 1.27,0.65, height 1.14
FP-IPB042N10N3GATMA1_D2PAK-MFG [mm]
  rrect7% 1.35x4.6 smd paste-1000 mask+0: 1(-2.54,-5.775) 3(2.54,-5.775)
  rrect1% 10.8x9.4 smd paste-1000 mask+0: 4(0,3.375)
  silkscreen extent -5.1,-2.73 5.1,-1.7, body extent -5.5,-8.18 5.5,8.18, height 0.25
FP-RK73H1JTTD1000F_0603-MFG [mm]
  rrect20% 0.5x0.6 smd paste+0 mask+0: 1(-0.75,0) 2(0.75,0)
  silkscreen extent -0.13,-0.45 0.13,0.45, body extent -0.8,-0.4 0.8,0.4, height 0.55
FP-RLTI-1387_PTH_CMC_0IN38_0IN60-MFG [mm]
  rrect5% 2.05x2.05 hole 1.35 paste-1000: 1(-5.08,-3.175)
  round 2.05 hole 1.35 paste-1000: 2(-5.08,3.175) 3(5.08,3.175) 4(5.08,-3.175)
  silkscreen extent -7.62,-5.55 7.62,4.83, body extent -7.72,-4.93 7.72,4.93, height 0.25
FP-RLTI-1457_PTH14_0IN93_0IN93-MFG [mm]
  rrect8% 1.3x1.3 hole 0.8 paste-1000 mask+0: 1(-10.198,10.173)
  round 1.3 hole 0.8 paste-1000 mask+0: 2(-10.198,6.363) 3(-10.198,2.553) 4(-10.198,-2.553) 5(-10.198,-6.363) 6(-10.198,-10.173) 7(10.198,-10.325) 8(10.198,-7.734) 9(10.198,-5.144) 10(10.198,-2.553) 11(10.198,2.553) 12(10.198,5.144) 13(10.198,7.734) 14(10.198,10.325)
  silkscreen extent -12.54,-11.81 11.81,11.81, body extent -11.91,-11.91 11.91,11.91, height 0.25
FP-RMCF1206ZT0R00_1206-MFG [mm]
  rrect10% 1x1.6 smd paste+0 mask+0: 1(-1.6,0) 2(1.6,0)
  silkscreen extent -0.72,-0.87 0.72,0.87, body extent -1.6,-0.8 1.6,0.8, height 0.7
FP-TLP383(GR-TPL,E_SO6-4-MFG [mm]
  rrect13% 1.3x0.8 smd paste+0 mask+0: 1(-4.75,1.27) 3(-4.75,-1.27) 4(4.75,-1.27) 6(4.75,1.27)
  silkscreen extent -3.7,-2.02 3.7,2.02, body extent -5.01,-1.92 5.01,1.92, height 2.3
FP-XGL3530_SMT_IND_3MM2_3MM5-MFG [mm]
  rrect12% 0.81x3.2 smd paste+0 mask+0: 1(-0.9,0) 2(0.9,0)
  silkscreen extent -2.33,-1.97 1.68,1.97, body extent -1.78,-1.92 1.78,1.92, height 0.25
FUSE_392 [mm] "LITTELFUSE"
  round 1.7 hole 1.05: 1(-2.54,0) 2(2.54,0)
  silkscreen extent -4.32,-2.03 4.32,2.03, body extent -4.25,-2 4.25,2, height 8
Keystone5011 [mil] "Keystone Multipurpose loops"
  round 87 hole 63: 1(0,0)
  silkscreen extent -70,-70 70,70, body extent -63,-63 63,62, height 319
Keystone5012 [mil] "Keystone Multipurpose loops"
  round 87 hole 63: 1(0,0)
  body extent -63,-63 63,62, height 319
On-Shore_ED120_2DS [mm] "ONSHORE"
  rrect5% 2x2 hole 1.25: 1(-2.54,0)
  round 2 hole 1.25: 2(2.54,0)
  silkscreen extent -5.6,-4 5.12,5, body extent -5.78,-4 5.08,5, height 13
PSG_1000x1150 [mm] "United Chemi-Con"
  rrect7% 1.5x1.5 hole 0.85: 1(-2.5,0)
  round 1.5 hole 0.85: 2(2.5,0)
  silkscreen extent -5.3,-5.3 5.3,5.3, body extent -5.25,-5.25 5.25,5.25, height 13.01
RESC1005X40X25LL05T05 [mm] "Chip Resistor, 2-Leads, Body 1.00x0.50mm, IPC High Density"
  rect 0.45x0.45 smd: 1(-0.4,0) 2(0.4,0)
  body extent -0.53,-0.27 0.53,0.28, height 0.4
RESC1005X40X25NL05T10 [mm] "Chip Resistor, 2-Leads, Body 1.00x0.50mm, IPC Medium Density"
  rect 0.6x0.55 smd: 1(-0.425,0) 2(0.425,0)
  body extent -0.53,-0.27 0.53,0.28, height 0.4
RTW0024B-MFG [mm]
  rrect42% 0.6x0.24 smd paste+0 mask+0: 1(-1.9,1.25) 2(-1.9,0.75) 3(-1.9,0.25) 4(-1.9,-0.25) 5(-1.9,-0.75) 6(-1.9,-1.25) 13(1.9,-1.25) 14(1.9,-0.75) 15(1.9,-0.25) 16(1.9,0.25) 17(1.9,0.75) 18(1.9,1.25)
  rrect42% 0.24x0.6 smd paste+0 mask+0: 7(-1.25,-1.9) 8(-0.75,-1.9) 9(-0.25,-1.9) 10(0.25,-1.9) 11(0.75,-1.9) 12(1.25,-1.9) 19(1.25,1.9) 20(0.75,1.9) 21(0.25,1.9) 22(-0.25,1.9) 23(-0.75,1.9) 24(-1.25,1.9)
  rrect4% 2.45x2.45 smd paste-1000 mask+0: 25(0,0)
  silkscreen extent -2.62,-2.05 2.05,2.05, body extent -2,-2 2,2, height 0.8
SMA [mm] "Molded Diode, 2-Leads, Body 4.3x2.6mm, IPC Medium Density, based on OnSemi component dimensions and land pattern"
  rect 2x2 smd: 1(-2,0) 2(2,0)
  silkscreen extent -3.33,-1.57 2.79,1.57, body extent -2.6,-1.3 2.6,1.3, height 2.42
SOD-123H [mm] "SMT, 2-Leads, Body 3.5x1.6mm"
  rect 1.3x1.8 smd: 1(-1.5,0) 2(1.5,0)
  silkscreen extent -2.64,-1.3 2.3,1.3, body extent -1.9,-0.9 1.9,0.9, height 1
SOD-323 [mm] "NXP recommended land pattern"
  rect 0.6x0.6 smd paste-0.05: 1(-1.1,0) 2(1.1,0)
  silkscreen extent -2.06,-0.86 1.53,0.86, body extent -1.3,-0.67 1.3,0.68, height 1.1
SOD-523 [mm] "NXP Semiconductor recommended land pattern, nominal STEP model"
  rect 0.8x0.6 smd paste-0.05: 1(-0.55,0) 2(0.55,0)
  silkscreen extent -1.65,-0.66 1.2,0.66, body extent -0.8,-0.4 0.8,0.4, height 0.72
SOT-23L [mm] "SOT23, 3-Leads, Body 2.9x1.3mm, Pitch 0.95mm, Lead Span 2.5mm, IPC High Density"
  rrect50% 0.8x0.6 smd: 1(-1.1,0.95) 2(-1.1,-0.95) 3(1.1,0)
  silkscreen extent -1.5,-1.5 0.7,1.5, body extent -1.16,-1.45 1.21,1.45, height 1
SOT-323 [mm] "Diodes Inc recommended land pattern.  2016-02-24"
  rrect21% 0.6x0.47 smd: 1(-0.95,0.65) 2(-0.95,-0.65) 3(0.95,0)
  silkscreen extent -1.14,-1.22 0.77,1.22, body extent -1.13,-1.13 1.12,1.12, height 1.13
UVC_1000x1600 [mm] "TH, 2-Leads, Dia 10mm, Lead Spacing 5mm"
  rect 1.275x1.275 hole 0.85: 1(-2.5,0)
  round 1.275 hole 0.85: 2(2.5,0)
  silkscreen extent -5.25,-5.25 5.25,5.25, body extent -5.25,-5.25 5.26,5.25, height 18.01
WCAP-FTX2_1500x850 [mm] "TH, 2-Leads, Body 15x8.5mm"
  rrect50% 1.35x1.35 hole 0.9: 1(-6.25,0)
  round 1.35 hole 0.9: 2(6.25,0)
  body extent -7.5,-4.25 7.5,4.25, height 14
Z4-D [mm] "SMD, 4-Leads, Body 8.1x10.5mm"
  rect 4.7x2.4 smd: 1(-3.7,2.55) 2(3.7,2.55) 3(3.7,-2.55) 4(-3.7,-2.55)
  silkscreen extent -5.3,-4.1 5.3,4.1, body extent -5.3,-4.1 5.3,4.1, height 1.56

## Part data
C1: library part CMP-0078358-1, "CAP, CERM, 2200 pF, X1 400 VAC/Y1 400 VAC, +/- 20%, Y5V, D9xL13mm", Cap_Case=9x13mm, Manufacturer=Kemet, Supplier Part Number 1=399-9487-1-ND, TempCo=Y5V, Tolerance_%=20%, ValueDisplayed=2200pF
C2: library part CMP-0008909-2, "CAP, CERM, 1000 pF, 630 V, +/- 10%, X7R, 1206", Cap_Case=1206, Manufacturer=MuRata, Supplier Part Number 1=490-3506-1-ND, TempCo=X7R, Tolerance_%=10%, Value1=Unknown, Value2=630V, ValueDisplayed=1000pF
C3 C4: library part CMP-0009076-1, "CAP, CERM, 0.1 uF, 630 V, +/- 10%, X7R, 1210", Cap_Case=1210, Manufacturer=Kemet, Supplier Part Number 1=399-13490-1-ND, TempCo=X7R, Tolerance_%=10%, Value1=Unknown, Value2=630V, ValueDisplayed=0.1uF
C5: library part CMP-0088960-1, "Cap Aluminum Lytic 22uF 450V 20% (18 X 16mm) Radial 7.5mm 340mA 10000h 105C", Digikey Part Number=1189-3181-ND, Leakage Current=298uA, Manufacturer=Rubycon, Mouser Part Number=232-450BXW22MEFR18X1, Operating Temperature Range="-40°C to +105°C", Tolerance_%=20%, ValueDisplayed=22uF
C6: library part CMP-0084596-1, "CAP, Film, 0.33 µF, X2 275 VAC, +/- 10%, TH", Cap_Case=15x8.5mm, Manufacturer="Wurth Elektronik", Tolerance_%=10%, ValueDisplayed=0.33µF
C7: library part CMP-0860955-2, "CAP, AL, 15 µF, 400 V, +/- 20%, AEC-Q200 Grade 2, TH", Cap_Case=10x16, Manufacturer=Nichicon, Tolerance_%=20%, Value2=400V, ValueDisplayed=15µF
C8 C9: library part CMP-0009224-2, "CAP, CERM, 22 uF, 25 V, +/- 10%, X7R, 1210", Cap_Case=1210, Manufacturer=MuRata, Supplier Part Number 1=490-5313-1-ND, TempCo=X7R, Tolerance_%=10%, Value1=Unknown, Value2=25V, ValueDisplayed=22uF
C10: library part CMP-0012176-3, "CAP, Aluminum Polymer, 680 uF, 20 V, +/- 20%, 0.012 ohm, TH", Cap_Case=10x11.5, Manufacturer=Chemi-Con, Supplier Part Number 1=565-3623-ND, Tolerance_%=20%, Value1="0.012 ohm", Value2=20V, ValueDisplayed=680uF
C11: library part CMP-0064943-2, "CAP, CERM, 1000 pF, 250 V,+/- 10%, X7R, 0805", Cap_Case=0805, Manufacturer=TDK, Supplier Part Number 1=445-2277-1-ND, TempCo=X7R, Tolerance_%=10%, Value1=Unknown, Value2=250V, ValueDisplayed=1000pF
C12: library part CMP-0008251-2, "CAP, CERM, 1000 pF, 250 V, +/- 10%, X7R, 0805", Cap_Case=0805, Manufacturer=MuRata, Supplier Part Number 1=490-3525-1-ND, TempCo=X7R, Tolerance_%=10%, Value1=Unknown, Value2=250V, ValueDisplayed=1000pF
C13 C19: library part CMP-0085817-1, "CAP, CERM, 22 µF, 35 V,+/- 20%, X5R, 1210", Cap_Case=1210, Manufacturer="Taiyo Yuden", TempCo=X5R, Tolerance_%=20%, Value2=35V, ValueDisplayed=22µF
C14: library part CMP-0009078-1, "CAP, CERM, 10 uF, 25 V, +/- 10%, X7R, 1210", Cap_Case=1210, Manufacturer=Kemet, Supplier Part Number 1=399-8224-1-ND, TempCo=X7R, Tolerance_%=10%, Value1=Unknown, Value2=25V, ValueDisplayed=10uF
C15: library part CMP-0076706-1, "CAP, CERM, 4.7 µF, 25 V,+/- 10%, X7R, AEC-Q200 Grade 1, 0805", Cap_Case=2x1.25x1.25mm, Manufacturer=TDK, Supplier Part Number 1=445-6967-1-ND, TempCo=X7R, Tolerance_%=10%, Value2=25V, ValueDisplayed=4.7µF
C16 C28 C29: library part CMP-0006348-2, "CAP, CERM, 22 pF, 50 V, +/- 5%, C0G/NP0, AEC-Q200 Grade 1, 0402", Cap_Case=0402, Manufacturer=MuRata, Supplier Part Number 1=490-9648-1-ND, TempCo=C0G/NP0, Tolerance_%=5%, Value1=Unknown, Value2=50V, ValueDisplayed=22pF
C17 C21: library part CMP-0006675-2, "CAP, CERM, 0.1 uF, 50 V, +/- 20%, X7R, 0402", Cap_Case=0402, Manufacturer=MuRata, Supplier Part Number 1=490-10701-1-ND, TempCo=X7R, Tolerance_%=20%, Value1=Unknown, Value2=50V, ValueDisplayed=0.1uF
C18: library part CMP-0008658-2, "CAP, CERM, 10 uF, 50 V, +/- 10%, X5R, 1206", Cap_Case=1206_180, Manufacturer=TDK, Supplier Part Number 1=445-5998-1-ND, TempCo=X5R, Tolerance_%=10%, Value1="0.002229 ohm", Value2=50V, ValueDisplayed=10uF
C20: library part CMP-0081062-1, "CAP, CERM, 10 µF, 25 V,+/- 5%, X7R, AEC-Q200 Grade 1, 1206", Cap_Case=1206_180, Manufacturer=Kemet, Supplier Part Number 1=399-15734-1-ND, TempCo=X7R, Tolerance_%=5%, Value2=25V, ValueDisplayed=10µF
C22 C26: library part CMP-0006687-2, "CAP, CERM, 330 pF, 50 V, +/- 10%, X7R, 0402", Cap_Case=0402, Manufacturer=MuRata, Supplier Part Number 1=490-3247-1-ND, TempCo=X7R, Tolerance_%=10%, Value1=Unknown, Value2=50V, ValueDisplayed=330pF
C23: library part CMP-0007067-4, "CAP, CERM, 1 uF, 35 V, +/- 10%, X7R, AEC-Q200 Grade 1, 0603", Cap_Case=0603, Manufacturer=TDK, Supplier Part Number 1=445-174215-1-ND, TempCo=X7R, Tolerance_%=10%, Value1="0.005522 ohm", Value2=35V, ValueDisplayed=1uF
C24: library part CMP-0006679-2, "CAP, CERM, 0.015 uF, 50 V, +/- 10%, X7R, 0402", Cap_Case=0402, Manufacturer=MuRata, Supplier Part Number 1=490-4517-1-ND, TempCo=X7R, Tolerance_%=10%, Value1=Unknown, Value2=50V, ValueDisplayed=0.015uF
C25 C27: library part CMP-0006410-2, "CAP, CERM, 100 pF, 50 V, +/- 5%, C0G/NP0, 0402", Cap_Case=0402, Manufacturer=MuRata, Supplier Part Number 1=81-GRM1555C1H101JA1D, TempCo=C0G/NP0, Tolerance_%=5%, Value1=Unknown, Value2=50V, ValueDisplayed=100pF
C30: library part CMP-0006674-2, "CAP, CERM, 0.01 uF, 50 V, +/- 10%, X7R, 0402", Cap_Case=0402, Manufacturer=MuRata, Supplier Part Number 1=490-4516-1-ND, TempCo=X7R, Tolerance_%=10%, Value1=Unknown, Value2=50V, ValueDisplayed=0.01uF
C31: library part CMP-0006648-2, "CAP, CERM, 0.22 uF, 16 V, +/- 10%, X7R, 0402", Cap_Case=0402, Manufacturer=MuRata, Supplier Part Number 1=490-5418-1-ND, TempCo=X7R, Tolerance_%=10%, Value1=Unknown, Value2=16V, ValueDisplayed=0.22uF
C32: library part CMP-0009174-2, "CAP, CERM, 22 uF, 16 V, +/- 10%, X7R, 1210", Cap_Case=1210, Manufacturer=MuRata, Supplier Part Number 1=490-5242-1-ND, TempCo=X7R, Tolerance_%=10%, Value1=Unknown, Value2=16V, ValueDisplayed=22uF
D1: library part CMP-0084982-1, "Diode, TVS, Uni, 150 V, 243 Vc, 400 W, 1.6 A, SMA", Manufacturer=Littelfuse, Value1=243V
D2: library part CMP-0077082-2, "Diode, Standard Recovery Rectifier, 1000 V, 1 A, AEC-Q101, SMA", Manufacturer="ON Semiconductor", Value1=1A, Value2=1.1V
D3 D6: library part CMP-0029199-2, "Diode, Superfast Rectifier, 200 V, 1 A, 3.5x1.6mm", Manufacturer="Comchip Technology", Value1=1A, Value2=0.95V
D4: library part CMP-0084980-1, "Diode, TVS, Uni, 120 V, 193 Vc, 400 W, 2.1 A, SMA", Manufacturer=Littelfuse, Value1=193V
D5: library part CMP-0029006-2, "Diode, Ultrafast, 100 V, 0.25 A, SOD-323", Manufacturer=Nexperia, Value1=0.25A, Value2=1.4V
D7: library part CMP-0087587-1, "Diode, TVS, Bi, 18 V, SOD-323", Manufacturer="Bourns Inc."
D8: library part CMP-0028437-2, "Diode, Schottky, 40 V, 0.2 A, SOT-323", Manufacturer="Diodes Inc.", Value1=0.2A, Value2=0.8V
D9: library part CMP-0076957-3, "Diode, Switching, 75 V, 0.3 A, SOD-523", Manufacturer="Micro Commercial Components", Value1=0.3A, Value2=1.25V
D10: library part CMP-0005889-5, "Diode, Zener, 39 V, 350 mW, AEC-Q101, SOD-523", Manufacturer="Diodes Inc.", Power_W=350mW, Value1=0.35W
D11: library part CMP-0085774-1, "Diode, Zener, 27 V, 300 mW, AEC-Q101, SOD-323", Manufacturer="ON Semiconductor", Power_W=300mW, Value1=0.3W
DB1: "Diode, P-N-Bridge, 600 V, 4 A, Z4-D", Manufacturer="Comchip Technology", Supplier Part Number 1=641-1502-1-ND, Value1=4A, Value2=0.95V
F1: library part CMP-0003561-2, "Fuse, 3.15 A, 250VAC/VDC, TH", Irating_A=3.15A, Manufacturer=Littelfuse, Supplier Part Number 1=F5504CT-ND
J1 J2 J3: library part CMP-0074910-1, "Terminal Block, 5.08 mm, 2x1, Brass, TH", Color=Blue, Current_A=15A, Manufacturer="On-Shore Technology", Supplier Part Number 1=ED1609-ND, Voltage_V=300V
L1: library part CMP-0087546-1, "WE-FI Leaded Toroidal Line Choke", Manufacturer=Wurth
L2: library part CMP-0092946-1, "Common Mode Choke, 2.3mH 35%, 0.6x0.38x0.75 IN", Manufacturer=Renco, Operating Temperature Range=to, Test Frequency=10kHz, Tolerance_%=35%
L3: library part CMP-0092762-2, "Power Inductor, shielded, composite, 20% tol, SMT, RoHS, halogen-free   USD 0.580", Manufacturer=Coilcraft, Operating Temperature Range="to +165°C", Self Resonant Frequency=43MHz, Test Frequency=1MHz, Tolerance_%=20%
Q1: library part CMP-0092601-1, "N-Channel 150 V 114A (Tc) 214W (Tc) Surface Mount, Wettable Flank PG-TSON-8-3", Digikey Part Number=448-BSC074N15NS5ATMA1CT-ND, Drain To Source Breakdown Voltage=150V, Input Capacitace At Vds="3100pF @ 75V", Manufacturer=Infineon, Mouser Part Number=726-BSC074N15NS5ATMA, Operating Temperature Range="-55°C to +175°C", Power_W=214W, Pulse Drain Current=456A, Typ Forward Diode Voltage=0.85V
Q2: library part CMP-0083711-2, "MOSFET, N-CH, 700 V DPAK", Alternate Manufacturer=None, Manufacturer="Infineon Technologies", Value1="? ohm", Value2="20 nC"
Q3: library part CMP-0081263-2, "MOSFET, N-CH, Depletion Mode, 800 V, SOT-23", Alternate Manufacturer=None, Manufacturer=IXYS, Supplier Part Number 1=CLA4160-1-ND, Value1="? ohm", Value2="? nC"
Q4: library part CMP-0077878-2, "Transistor, PNP, 40 V, 0.2 A, AEC-Q101, SOT-323", Manufacturer="Diodes Inc.", Value1="0.2 A", Value2=300.0
Q5: library part CMP-0087591-1, "N-Channel 100V 100A (Tc) 214W (Tc) Surface Mount D²PAK (TO-263AB)", Drain To Source Breakdown Voltage=100V, Input Capacitace At Vds="6320pF @ 50V", Manufacturer=Infineon, Max Forward Diode Voltage=1.2V, Mouser Part Number=726-IPB042N10N3GATMA, Operating Temperature Range="-55°C to +175°C", Power_W=214W, Pulse Drain Current=548A, Typ Forward Diode Voltage=1V
R1: library part CMP-0020554-3, "RES, 470 k, 5%, 0.125 W, AEC-Q200 Grade 0, 0805", Manufacturer=Vishay-Dale, Power_W=125mW, Supplier Part Number 1=541-470KACT-ND, TempCo="200 ppm/C", Tolerance_%=5%, Value2=0.125W, Value_Code=470k
R2: library part CMP-0020464-3, "RES, 15, 5%, 0.125 W, AEC-Q200 Grade 0, 0805", Manufacturer=Vishay-Dale, Power_W=125mW, Supplier Part Number 1=541-15ACT-ND, TempCo="200 ppm/C", Tolerance_%=5%, Value2=0.125W, Value_Code=15R0, ValueDisplayed=15
R3: library part CMP-0021045-3, "RES, 20.5, 1%, 0.125 W, AEC-Q200 Grade 0, 0805", Manufacturer=Vishay-Dale, Power_W=125mW, Supplier Part Number 1=541-20.5CCT-ND, TempCo="100 ppm/C", Tolerance_%=1%, Value2=0.125W, Value_Code=20R5, ValueDisplayed=20.5
R4: library part CMP-0018578-3, "RES, 10, 5%, 0.25 W, AEC-Q200 Grade 0, 1206", Manufacturer=Vishay-Dale, Power_W=250mW, Supplier Part Number 1=541-10ECT-ND, TempCo="200 ppm/C", Tolerance_%=5%, Value2=0.25W, Value_Code=10R0, ValueDisplayed=10
R5 R39: library part CMP-0081622-1, "RES, 1.00, 1%, 0.125 W, 0402", Manufacturer="Stackpole Electronics Inc", Power_W=125mW, Supplier Part Number 1=CSR0402FK1R00CT-ND, TempCo="200 ppm/C", Tolerance_%=1%, Value2=0.125W, Value_Code=1R00, ValueDisplayed=1.00
R6: library part CMP-0089152-1, "100 Ohms ±1% 0.125W, 1/8W Chip Resistor 0603 (1608 Metric) Automotive AEC-Q200, Moisture Resistant Thick Film", Approved Alternate Part Number=541-1.00HHCT-ND, Digikey Part Number=2019-RK73H1JTTD1000FCT-ND, Manufacturer="KOA Speer", Mouser Part Number=660-RK73H1JTTD1000F, Operating Temperature Range="-55°C to +155°C", Power=100mW, TempCo=100ppm/°C, Tolerance_%=1%, Voltage=75V
R7 R20 R35: library part CMP-0025958-3, "RES, 10.0 k, 1%, 0.063 W, AEC-Q200 Grade 0, 0402", Manufacturer=Vishay-Dale, Power_W=63mW, Supplier Part Number 1=541-10.0KLCT-ND, TempCo="100 ppm/C", Tolerance_%=1%, Value2=0.063W, Value_Code=10k0, ValueDisplayed=10.0k
R8 R32: library part CMP-0026859-2, "RES, 1.0 M, 5%, 0.063 W, AEC-Q200 Grade 0, 0402", Manufacturer=Vishay-Dale, Power_W=63mW, Supplier Part Number 1=541-1.0MJCT-ND, TempCo="200 ppm/C", Tolerance_%=5%, Value2=0.063W, Value_Code=1M00, ValueDisplayed=1.0M
R9: library part CMP-0026570-2, "RES, 80.6 k, 1%, 0.063 W, AEC-Q200 Grade 0, 0402", Manufacturer=Vishay-Dale, Power_W=63mW, Supplier Part Number 1=541-80.6KLCT-ND, TempCo="100 ppm/C", Tolerance_%=1%, Value2=0.063W, Value_Code=80k6, ValueDisplayed=80.6k
R10: library part CMP-0021844-3, "RES, 0.68, 1%, 0.125 W, AEC-Q200 Grade 0, 0805", Manufacturer=Panasonic, Power_W=125mW, Supplier Part Number 1=P.68DCT-ND, TempCo="250 ppm/C", Tolerance_%=1%, Value2=0.125W, Value_Code=R680, ValueDisplayed=0.68
R11: library part CMP-0015175-2, "RES, 0.22, 1%, 0.5 W, 1210", Manufacturer=Rohm, Power_W=500mW, Supplier Part Number 1=RHM.22SCT-ND, TempCo="200 ppm/C", Tolerance_%=1%, Value2=0.5W, Value_Code=R220, ValueDisplayed=0.22
R12 R28: library part CMP-0026436-2, "RES, 511, 1%, 0.063 W, AEC-Q200 Grade 0, 0402", Manufacturer=Vishay-Dale, Power_W=63mW, Supplier Part Number 1=541-511LCT-ND, TempCo="100 ppm/C", Tolerance_%=1%, Value2=0.063W, Value_Code=511R, ValueDisplayed=511
R13 R15: library part CMP-0026213-2, "RES, 27.4 k, 1%, 0.063 W, AEC-Q200 Grade 0, 0402", Manufacturer=Vishay-Dale, Power_W=63mW, Supplier Part Number 1=541-27.4KLCT-ND, TempCo="100 ppm/C", Tolerance_%=1%, Value2=0.063W, Value_Code=27k4, ValueDisplayed=27.4k
R14: library part CMP-0025992-3, "RES, 25.5 k, 1%, 0.063 W, 0402", Manufacturer=Vishay-Dale, Power_W=63mW, Supplier Part Number 1=541-12.4KLCT-ND, TempCo="100 ppm/C", Tolerance_%=1%, Value2=0.063W, Value_Code=12k4, ValueDisplayed=25.5k
R16: library part CMP-0026071-3, "RES, 1.00 k, 1%, 0.063 W, AEC-Q200 Grade 0, 0402", Manufacturer=Vishay-Dale, Power_W=63mW, Supplier Part Number 1=541-1.00KLCT-ND, TempCo="100 ppm/C", Tolerance_%=1%, Value2=0.063W, Value_Code=1k00, ValueDisplayed=1.00k
R17: library part CMP-0026229-2, "RES, 25.5 k, 1%, 0.063 W, 0402", Manufacturer=Vishay-Dale, Power_W=63mW, Supplier Part Number 1=541-2.10KLCT-ND, TempCo="100 ppm/C", Tolerance_%=1%, Value2=0.063W, Value_Code=2k10, ValueDisplayed=25.5k
R18: library part CMP-0027004-2, "RES, 0, 5%, 0.063 W, 0402", Manufacturer="Yageo America", Power_W=63mW, Supplier Part Number 1=311-0.0JRCT-ND, TempCo="200 ppm/C", Tolerance_%=5%, Value2=0.063W, Value_Code=0000, ValueDisplayed=0
R19: library part CMP-1011-00001-2, Manufacturer="Yageo / Phycomp"
R21: library part CMP-0026162-2, "RES, 20.0 k, 1%, 0.063 W, AEC-Q200 Grade 0, 0402", Manufacturer=Vishay-Dale, Power_W=63mW, Supplier Part Number 1=541-20.0KLCT-ND, TempCo="100 ppm/C", Tolerance_%=1%, Value2=0.063W, Value_Code=20k0, ValueDisplayed=20.0k
R22: library part CMP-1011-00620-2, Manufacturer=Panasonic
R23: library part CMP-0026301-2, "RES, 340, 1%, 0.063 W, AEC-Q200 Grade 0, 0402", Manufacturer=Vishay-Dale, Power_W=63mW, Supplier Part Number 1=541-340LCT-ND, TempCo="100 ppm/C", Tolerance_%=1%, Value2=0.063W, Value_Code=340R, ValueDisplayed=340
R24: library part CMP-0026063-3, "RES, 191 k, 1%, 0.063 W, AEC-Q200 Grade 0, 0402", Manufacturer=Vishay-Dale, Power_W=63mW, Supplier Part Number 1=541-191KLCT-ND, TempCo="100 ppm/C", Tolerance_%=1%, Value2=0.063W, Value_Code=191k
R25: library part CMP-0026327-2, "RES, 39.2 k, 1%, 0.063 W, AEC-Q200 Grade 0, 0402", Manufacturer=Vishay-Dale, Power_W=63mW, Supplier Part Number 1=541-39.2KLCT-ND, TempCo="100 ppm/C", Tolerance_%=1%, Value2=0.063W, Value_Code=39k2, ValueDisplayed=39.2k
R26: library part CMP-0078669-1, "RES, 10.0 k, 1%, 0.063 W, 0402", Manufacturer="Yageo America", Power_W=63mW, Supplier Part Number 1=311-10.0KLRCT-ND, TempCo="100 ppm/C", Tolerance_%=1%, Value2=0.063W, Value_Code=10k0, ValueDisplayed=10.0k
R27: library part CMP-0026333-2, "RES, 3.32 k, 1%, 0.063 W, AEC-Q200 Grade 0, 0402", Manufacturer=Vishay-Dale, Power_W=63mW, Supplier Part Number 1=541-3.32KLCT-ND, TempCo="100 ppm/C", Tolerance_%=1%, Value2=0.063W, Value_Code=3k32, ValueDisplayed=3.32k
R29: library part CMP-0026038-3, "RES, 169 k, 1%, 0.063 W, AEC-Q200 Grade 0, 0402", Manufacturer=Vishay-Dale, Power_W=63mW, Supplier Part Number 1=541-169KLCT-ND, TempCo="100 ppm/C", Tolerance_%=1%, Value2=0.063W, Value_Code=169k
R30: library part CMP-0026023-3, "RES, 154 k, 1%, 0.063 W, AEC-Q200 Grade 0, 0402", Manufacturer=Vishay-Dale, Power_W=63mW, Supplier Part Number 1=541-154KLCT-ND, TempCo="100 ppm/C", Tolerance_%=1%, Value2=0.063W, Value_Code=154k
R31: library part CMP-0026609-3, "RES, 93.1 k, 1%, 0.063 W, AEC-Q200 Grade 0, 0402", Manufacturer=Vishay-Dale, Power_W=63mW, Supplier Part Number 1=541-93.1KLCT-ND, TempCo="100 ppm/C", Tolerance_%=1%, Value2=0.063W, Value_Code=93k1, ValueDisplayed=93.1k
R33: library part CMP-0026591-2, "RES, 8.66 k, 1%, 0.063 W, AEC-Q200 Grade 0, 0402", Manufacturer=Vishay-Dale, Power_W=63mW, Supplier Part Number 1=541-8.66KLCT-ND, TempCo="100 ppm/C", Tolerance_%=1%, Value2=0.063W, Value_Code=8k66, ValueDisplayed=8.66k
R34: library part CMP-0081856-1, "RES, 0, 0%, 0.2 W, AEC-Q200 Grade 0, 0402", Manufacturer=Vishay-Dale, Power_W=200mW, Supplier Part Number 1=541-0.0YBTR-ND, Tolerance_%=0%, Value2=0.2W, Value_Code=0
R36: library part CMP-0026367-2, "RES, 40.2 k, 1%, 0.063 W, AEC-Q200 Grade 0, 0402", Manufacturer=Vishay-Dale, Power_W=63mW, Supplier Part Number 1=541-40.2KLCT-ND, TempCo="100 ppm/C", Tolerance_%=1%, Value2=0.063W, Value_Code=40k2, ValueDisplayed=40.2k
R37 R38: library part CMP-0093609-1, "0Ω ±0 0.25W 1206 Thick Film Chip Resistor AEC-Q200 compliant", Manufacturer="Stackpole Electronics", Operating Temperature Range="-55°C to +155°C", Power_W=250mW
RT1: library part CMP-0002523-3, "Thermistor NTC, 47k ohm, 5%, 0603", Manufacturer=MuRata, Power_W=100mW, Supplier Part Number 1=490-2428-1-ND, Tolerance_%=5%
T1: library part CMP-0097858-1, "HIGH EFFICIECNY FLYBACK TRANSFORMER, PMP23331", Manufacturer="Renco Electronics", Operating Temperature Range=to, Voltage_Isolation_Vrms=3kV
TP1 TP3: library part CMP-0055149-1, "Test Point, Multipurpose, White, TH", Color=White, Manufacturer=Keystone, PartNumber=5012, Supplier Part Number 1=36-5012-ND
TP2: library part CMP-0055148-1, "Test Point, Multipurpose, Black, TH", Color=Black, Manufacturer=Keystone, PartNumber=5011, Supplier Part Number 1=36-5011-ND
U1: library part CMP-0092521-4, "3-V to 17-V, 300mA Low IQ Buck Converter in SOT583 Package", Manufacturer="Texas Instruments", Max Supply Voltage=17V, Min Supply Voltage=3V, Nominal Supply Current=5mA, Operating Temperature Range="-40°C to +125°C", Output Voltage=0.4-5.5V, Switching Frequency=1/2.5MHz
U2: library part CMP-0860377-2, "4-A/6-A, Single-Channel Reinforced Isolation Gate Driver with High Noise Immunity, DWV0008A (SOIC-8)", Alternate Manufacturer="Texas Instruments"
U3: library part CMP-0094229-1, "Zero-Voltage-Switching Flyback Controller with Dedicated Synchronous Rectifier Gate-Drive", Manufacturer="Texas Instruments", Max Supply Voltage=34V, Min Supply Voltage=14V, Nominal Supply Current=235-3000uA, Operating Temperature Range="-40°C to +125°C", Switching Frequency=1.5kHz
U4: library part CMP-0087394-2, "Optoisolator Transistor Output 5000Vrms 1 Channel 6-SO", Manufacturer=Toshiba
U5: library part CMP-0066199-1, "2.5V Low Iq Adjustable Precision Shunt Regulator, DBZ0003A (SOT-23-3)", Alternate Manufacturer="Texas Instruments"

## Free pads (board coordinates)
  round 60 hole 118.11: 1(3325,3080) 2(280,3100) 3(270,280) 4(3340,265)

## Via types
v1: diameter 27.56, hole 11.81, Top Layer to Bottom Layer, tented both sides, 30 vias
v2: diameter 27.56, hole 11.81, Top Layer to Bottom Layer, tented top, 22 vias
v3: diameter 26, hole 8, Top Layer to Bottom Layer, tented both sides, 11 vias
v4: diameter 19.68, hole 7.87, Top Layer to Bottom Layer, 5 vias
v5: diameter 27, hole 8, Top Layer to Bottom Layer, tented both sides, 4 vias
v6: diameter 27.56, hole 11.81, Top Layer to Bottom Layer, 4 vias

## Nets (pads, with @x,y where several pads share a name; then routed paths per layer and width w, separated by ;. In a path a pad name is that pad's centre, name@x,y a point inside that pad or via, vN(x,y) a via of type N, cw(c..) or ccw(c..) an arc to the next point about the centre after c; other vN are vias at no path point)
BUR: C26.1 R24.2 R25.1 U3.5 | length 341.5
  Signal Layer 1 w9.84: v1@1556.4,2311.9 v1(1559.42,2311.9) v1@1562.38,2314.85
  Signal Layer 1 w10: v1(1559.42,2311.9) 1572.52,2324 1728,2324 v1(1740,2334)
  Bottom Layer w7.87: U3.5@1538.49,2272.53 1538.49,2290.97 v1(1559.42,2311.9) 1557.1,2314.23 C26.1@1557.14,2349.3
  Bottom Layer w10: R24.2@1710,2305 1740,2305 v1(1740,2334)
CS: C25.1 Q4.3 R23.1 R32.2 U3.9 | length 907.2
  Signal Layer 2 w10: v1(1143,2370) 1170,2397 1582,2397 v1(1700,2278)
  Bottom Layer w8: U3.9@1583.77,2207.57 1601,2207.57 1614.11,2220.69 1635.37,2220.69 1654.29,2201.77 C25.1@1664.11,2201.77 ; 1700,2202 1737.59,2202 R23.1@1740,2204.41
  Bottom Layer w10: Q4.3@1112.61,2341 v1(1143,2370) ; C25.1@1664,2204 1666,2202 1700,2202 R32.2@1700,2230 v1(1700,2278)
FB: C22.2 R21.1 U3.6 | length 92.7
  Bottom Layer w7.87: U3.6@1558.18,2272.53 1594.9,2309.25 1594.9,2312.88 R21.1@1595,2350
FLT: C27.2 R27.2 U3.1 | length 98.2
  Bottom Layer w7.87: C27.2@1401.98,2311.9 1402.3,2311.58 C27.2@1404.27,2311.58 ; 1423.95,2291.9 1440.38,2291.9 U3.1@1459.75,2272.53
  Bottom Layer w8: R27.2@1375,2312 C27.2@1405.98,2312 ; C27.2@1415,2310.91 1423.95,2291.9
GND_C: C14.2 C15.2 C32.2 J3.1 R9.1 R13.1 T1.14 U1.5
  other v3: 860,2595 860,2680.83 885,2755 1086.95,2755 1086.95,2796.5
